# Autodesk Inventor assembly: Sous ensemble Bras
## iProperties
Created: 2004-11
Part Number: Sous ensemble Bras
Document SubType Name: Assembly
Designer: Bruno
Manufacturer: Standard
Standards Organization: Custom
Norme de conversion: STEP AP203
Nom du fichier: Take Out.stp
Préprocesseur: Mechanical Desktop 2005
Postprocesseur: Build: 096e, Release: 9 RTM - Date: Thu 06/17/2004
Unités envoyées: MILLIMETERS
Incertitude: 1.0000000000000002e-06
Author: Bruno
